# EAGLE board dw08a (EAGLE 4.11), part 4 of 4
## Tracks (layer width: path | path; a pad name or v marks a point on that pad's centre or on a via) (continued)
O_BAC10  (via drill 0.61) (continued)
  Bottom 0.152: v119.63,104.71 134.62,119.7 134.62,121.47 A14.E2 | v132.84,83 132.84,79.44 v128.02,74.61
O_BAC11  (via drill 0.61)
  Top 0.152: v155.45,25.08 155.45,28 150.5,32.96 150.5,34.73 138.81,46.42 138.81,46.93 137.03,48.7 137.03,50.48 136.78,50.74 136.78,52.64 133.6,55.82 133.6,56.96 v125.73,64.83 | v150.5,90.49 150.5,90.61 135.64,105.47 135.25,105.47 v130.68,110.05
  Bottom 0.152: v155.45,25.08 151.38,21.02 148.34,21.02 B13.S2 | v125.73,64.83 125.73,65.98 148.46,88.71 148.72,88.71 v150.5,90.49 | v130.68,110.05 132.84,112.2 132.84,113.35 134.62,115.13 A14.H2
O_BREAK  (via drill 0.61)
  Top 0.152: v92.46,67.88 66.8,93.53 65.79,93.53 64.01,95.31 61.47,95.31 60.33,96.46 59.44,96.46 A20.P2 | v96.9,67.88 108.08,56.71 109.98,56.71 v138.18,28.51
  Bottom 0.152: v92.46,67.88 v96.9,67.88 | v138.18,28.51 138.18,25.46 137.03,24.32 137.03,23.18 135.25,21.4 B14.S2
O_BRKRQ  (via drill 0.61)
  Top 0.152: v44.7,80.71 50.04,75.37 50.04,73.6 50.42,73.22 50.42,62.93 79.88,33.47 79.88,29.65 82.17,27.37 83.44,27.37 B18.P2
  Bottom 0.152: v44.7,80.71 44.7,87.57 59.82,102.68 59.82,103.69 57.15,106.36 56.01,105.22 55.12,105.22 53.98,106.36 55.12,107.5 56.39,107.5 58.04,109.16 A20.K2
O_CAINCR  (via drill 0.61)
  Top 0.152: v31.5,101.16 31.88,100.78 31.88,96.2 35.05,93.03 35.05,86.68 40.01,81.72 40.01,72.58 40.39,72.2 40.51,72.2 71.12,41.59 71.12,40.45 B19.K2
  Bottom 0.152: v31.5,101.16 32.89,102.55 A22.M2
O_DATA00  (via drill 0.61)
  Top 0.152: v40.77,72.96 40.77,81.47 35.43,86.81 35.43,93.15 32.26,96.33 32.26,101.66 31.5,102.42 31.5,112.46 43.18,124.14 42.67,124.65 A21.D2
  Bottom 0.152: v40.77,72.96 40.77,64.58 39.37,63.18 39.37,61.66 33.66,55.94 33.66,53.15 B22.E2
O_DATA01  (via drill 0.61)
  Top 0.152: v18.8,79.31 19.18,78.93 19.18,64.45 21.08,62.55 21.08,60.13 33.02,48.2 33.02,46.8 B22.H2
  Bottom 0.152: v18.8,79.31 18.8,93.41 43.94,118.56 43.94,119.7 45.72,121.47 A21.E2
O_DATA02  (via drill 0.61)
  Top 0.152: v18.41,77.79 18.8,77.41 18.8,64.33 19.56,63.56 19.56,58.23 33.02,44.77 33.02,40.45 B22.K2
  Bottom 0.152: v18.41,77.79 19.56,78.93 19.56,87.82 43.94,112.2 43.94,113.35 45.72,115.13 A21.H2
O_DATA03  (via drill 0.61)
  Top 0.152: v16.38,72.58 16.38,55.05 17.4,54.04 17.4,53.53 33.02,37.91 33.02,34.1 B22.M2
  Bottom 0.152: v16.38,72.58 17.02,72.58 22.35,77.92 22.35,84.26 43.94,105.86 43.94,107 45.72,108.78 A21.K2
O_DATA04
  Bottom 0.152: B22.P2 32.64,27.37 28.19,27.37 19.05,36.51 17.91,35.37 17.02,35.37 6.22,46.16 6.22,61.28 25.27,80.33 25.27,80.83 43.94,99.5 43.94,100.65 45.72,102.42 A21.M2
O_DATA05  (via drill 0.61)
  Top 0.152: v67.69,58.61 67.69,59.37 59.94,67.12 59.94,68.64 48.13,80.45 48.13,94.3 46.35,96.08 A21.P2
  Bottom 0.152: v67.69,58.61 33.66,24.57 33.66,21.4 B22.S2
O_DATA06  (via drill 0.61)
  Top 0.152: v46.61,81.09 46.61,83 47.75,84.14 47.75,88.33 46.35,89.72 A21.S2
  Bottom 0.152: v46.61,81.09 20.95,55.44 20.95,53.15 B23.E2
O_DATA07
  Bottom 0.152: B23.H2 19.94,46.42 18.54,46.42 14.99,49.97 24.51,59.5 24.51,60.52 28.45,64.45 28.45,64.96 43.94,80.45 43.94,85.79 43.18,86.55 A21.T2
O_DATA08
  Bottom 0.152: B23.K2 20.32,40.45 20.32,44.01 14.35,49.97 24.13,59.75 24.13,60.64 28.07,64.58 28.07,65.72 42.55,80.2 A21.V2
O_DATA09  (via drill 0.61)
  Top 0.152: v1.65,57.09 20.32,38.42 20.32,34.1 B23.M2
  Bottom 0.152: v1.65,57.09 1.65,95.31 28.07,121.73 28.07,122.87 29.84,124.65 A22.D2
O_DATA10
  Bottom 0.152: B23.P2 19.94,27.37 18.54,27.37 4.7,41.21 5.84,42.35 5.84,93.15 31.24,118.56 31.24,119.7 33.02,121.47 A22.E2
O_DATA11  (via drill 0.61)
  Top 0.152: v14.61,98.74 0.89,85.03 0.89,56.71 19.56,38.04 19.56,26.48 20.32,25.72 20.32,21.4 B23.S2
  Bottom 0.152: v14.61,98.74 29.72,113.86 30.99,113.86 32.64,115.51 A22.H2
O_DATAIN  (via drill 0.61)
  Top 0.152: v37.47,77.28 37.85,76.9 37.85,70.29 54.48,53.66 54.48,48.7 68.2,34.99 68.2,34.48 71.37,31.3 75.06,31.3 83.82,22.54 83.82,21.4 B18.S2
  Bottom 0.152: v37.47,77.28 37.47,80.33 37.59,80.45 37.59,83.63 55.12,101.16 56.39,101.16 58.04,102.81 A20.M2
O_EXTA0  (via drill 0.61)
  Top 0.152: v15.24,112.08 15.62,111.7 15.62,99.25 35.43,79.44 35.43,61.4 42.8,54.04 42.8,53.02 71.12,24.7 71.12,21.4 B19.S2
  Bottom 0.152: v15.24,112.08 17.02,113.86 18.29,113.86 19.94,115.51 A23.H2
O_EXTA1
  Top 0.152: B19.P2 70.74,27.37 69.98,27.37 68.96,28.38 68.45,28.38 67.18,29.65 67.18,35.5 54.1,48.58 54.1,53.53 37.47,70.17 37.47,76.14 36.7,76.9 36.7,78.68 16,99.38 16,125.67 17.4,127.06 18.54,125.92 18.54,124.78 20.32,123 A23.E2
O_EXTA2
  Top 0.152: B19.M2 71.12,34.1 71.12,37.27 70.99,37.4 70.99,37.66 38.23,70.42 38.23,77.66 16.38,99.5 16.38,123.89 17.14,124.65 A23.D2
O_INIT  (via drill 0.61)
  Top 0.152: v194.44,19.49 191.64,19.49 157.1,54.04 156.59,54.04 144.65,65.98 144.15,65.98 139.06,71.06 139.06,71.44 133.1,77.41 133.1,77.66 132.08,78.68 132.08,80.2 A14.V2 | v196.85,21.78 196.98,21.78 197.74,21.02 B09.S2
  Bottom 0.152: v194.44,19.49 194.56,19.49 v196.85,21.78
O_IOP1  (via drill 0.61)
  Top 0.152: v186.69,78.42 207.65,57.47 207.65,56.33 B08.D2 | v183.64,77.41 182.75,77.41 146.56,113.6 145.16,113.6 144.91,113.86 140.97,113.86 v140.46,114.36
  Bottom 0.152: v186.69,78.42 184.66,78.42 v183.64,77.41 | v140.46,114.36 138.18,114.36 137.03,113.22 137.03,112.08 135.25,110.3 A14.K2
O_IOP2  (via drill 0.61)
  Top 0.152: v185.8,54.17 176.02,63.94 172.59,63.94 167.64,68.9 163.07,68.9 162.94,69.03 162.43,69.03 162.31,69.15 161.93,69.15 161.67,69.41 161.42,69.41 151.89,78.93 151.89,81.47 139.57,93.79 139.57,94.3 135.25,98.61 135.25,102.42 A14.M2 | v190.5,55.56 193.17,52.9 193.17,52.39 194.06,51.5 195.33,51.5 v207.77,39.05
  Bottom 0.152: v185.8,54.17 189.1,54.17 v190.5,55.56 | v207.77,39.05 210.19,39.05 210.44,39.31 B08.K2
O_IOP4  (via drill 0.61)
  Top 0.152: v117.86,79.31 117.86,75.5 127.25,66.1 127.25,64.83 135,57.09 135.13,57.09 135.51,56.71 135.51,54.93 137.92,52.51 137.92,51.88 138.3,51.5 138.3,50.61 139.19,49.72 139.19,46.55 175.77,9.97 179.58,9.97 180.97,8.57 184.4,8.57 v187.96,5.02 | v208.28,22.04 209.42,22.04 210.44,21.02 B08.S2
  Bottom 0.152: v117.86,79.31 117.98,79.44 117.98,81.47 132.97,96.46 134.24,96.46 A14.P2 | v187.96,5.02 187.96,5.4 194.82,12.26 198.5,12.26 v208.28,22.04
O_IRQ  (via drill 0.61)
  Top 0.152: v104.52,74.36 104.52,81.22 86.23,99.5 86.23,100.65 84.45,102.42 A18.M2
  Bottom 0.152: v104.52,74.36 85.22,55.05 85.22,51.88 84.45,51.12 84.45,46.8 B18.H2
O_LINE  (via drill 0.61)
  Top 0.152: v93.98,44.51 93.98,46.16 93.34,46.8 93.34,47.43 76.33,64.45 76.33,65.72 v71.25,70.8
  Bottom 0.152: v93.98,44.51 93.47,44.01 93.22,44.01 84.45,35.24 84.45,34.1 B18.M2 | v71.25,70.8 80.64,80.2 A18.V2
O_MB00  (via drill 0.61)
  Top 0.152: v133.35,137.73 159.89,137.73 161.04,136.59 163.32,136.59 163.7,136.97 168.28,136.97 v180.72,124.52 | v201.68,139.51 204.98,139.51 210.69,133.79 213.87,133.79 218.57,129.09 218.57,127.95 220.34,126.17 A07.D2
  Bottom 0.152: v133.35,137.73 121.41,125.79 119.76,125.79 A15.D2 | v180.72,124.52 180.72,125.16 191.64,136.08 193.8,136.08 196.85,139.13 199.26,139.13 199.64,139.51 v201.68,139.51
O_MB01  (via drill 0.61)
  Top 0.152: v198.25,125.73 199.77,124.21 210.19,124.21 211.07,123.32 211.71,123.32 220.34,114.68 220.34,114.3 220.85,113.79 221.23,113.79 223.39,111.63 223.39,110.24 A07.K2 | v196.85,124.33 185.8,124.33 184.78,125.35 184.28,125.35 v169.93,139.7
  Bottom 0.152: v196.85,124.33 v198.25,125.73 | v169.93,139.7 141.35,139.7 125.98,124.33 124.59,124.33 122.94,122.68 A15.E2
O_MB02  (via drill 0.61)
  Top 0.152: v217.55,82.55 217.42,82.55 213.23,86.74 213.23,87.38 211.33,89.28 210.82,89.28 210.69,89.41 210.57,89.41 210.57,89.53 210.44,89.53 210.44,89.66 210.31,89.66 210.31,89.79 210.19,89.79 210.19,89.92 210.06,89.92 210.06,90.04 207.52,92.58 207.39,92.58 207.39,92.71 207.26,92.71 207.26,92.84 207.14,92.84 207.14,92.96 207.01,92.96 207.01,93.09 206.88,93.09 206.88,93.22 204.34,95.76 204.22,95.76 204.22,95.89 204.09,95.89 204.09,96.01 203.96,96.01 203.96,96.14 203.84,96.14 203.84,96.27 203.71,96.27 203.71,96.39 201.17,98.93 201.04,98.93 201.04,99.06 200.91,99.06 200.91,99.19 200.79,99.19 200.79,99.31 200.66,99.31 200.66,99.44 200.53,99.44 200.53,99.57 197.99,102.11 197.87,102.11 197.87,102.23 197.74,102.23 197.74,102.36 197.61,102.36 197.61,102.49 197.49,102.49 197.49,102.62 197.36,102.62 197.36,102.74 194.82,105.28 194.69,105.28 194.69,105.41 194.56,105.41 194.56,105.54 194.44,105.54 194.44,105.66 194.31,105.66 194.31,105.79 194.18,105.79 194.18,105.92 191.64,108.46 191.52,108.46 191.52,108.58 191.39,108.58 191.39,108.71 191.26,108.71 191.26,108.84 191.13,108.84 191.13,108.97 191.01,108.97 191.01,111.63 190.12,112.52 190.12,115.32 188.72,116.71 186.56,116.71 183.13,120.14 179.32,120.14 178.94,120.52 178.56,120.52 v173.1,125.98 | v166.5,120.4 163.83,120.4 151.38,132.84 v142.88,132.84
  Bottom 0.152: v217.55,82.55 223.39,88.39 223.39,89.79 A07.S2 | v173.1,125.98 172.09,125.98 v166.5,120.4 | v142.88,132.84 140.84,132.84 125.98,117.98 124.59,117.98 122.94,116.33 A15.H2
O_MB03  (via drill 0.61)
  Top 0.152: v132.59,91.25 122.56,101.28 122.56,102.42 A15.M2 | v184.4,137.35 184.91,137.35 209.04,113.22 209.04,112.08 210.82,110.3 A08.K2
  Bottom 0.152: v132.59,91.25 134.11,91.25 134.49,91.63 134.87,91.63 136.27,93.03 136.27,93.41 147.19,104.33 150.88,104.33 158.62,112.08 158.62,115.76 178.94,136.08 183.13,136.08 v184.4,137.35
O_MB03\  (via drill 0.61)
  Top 0.152: v147.45,101.28 140.72,108.01 134.37,108.01 132.59,109.79 132.08,109.79 129.67,112.2 127.38,109.92 122.94,109.92 A15.K2 | v186.31,138.11 193.68,138.11 204.34,127.44 205.61,127.44 207.26,125.79 A08.D2
  Bottom 0.152: v147.45,101.28 149.48,101.28 v186.31,138.11
O_MB04  (via drill 0.61)
  Top 0.152: v175.26,136.21 182.88,136.21 191.64,127.44 192.91,127.44 194.56,125.79 A09.D2
  Bottom 0.152: v175.26,136.21 175.13,136.08 172.59,136.08 153.54,117.03 147.19,117.03 122.56,92.39 122.56,91.25 A15.S2
O_MB04\  (via drill 0.61)
  Top 0.152: v200.03,103.06 200.03,102.93 201.8,101.16 202.06,101.16 206.5,96.71 206.5,96.46 208.15,94.81 208.41,94.81 210.82,92.39 210.82,91.25 A08.S2 | v190.75,93.92 190.25,93.92 v185.29,98.87 | v175.64,90.36 174.75,90.36 173.48,91.63 169.54,91.63 146.81,114.36 145.54,114.36 v142.88,117.03
  Bottom 0.152: v200.03,103.06 199.9,103.06 v190.75,93.92 | v185.29,98.87 184.15,98.87 v175.64,90.36 | v142.88,117.03 140.34,117.03 136.65,113.35 136.65,112.84 124.33,100.52 124.33,99.38 122.56,97.6 A15.P2
O_MB05  (via drill 0.61)
  Top 0.152: v151.51,57.59 147.19,57.59 145.16,59.63 144.27,59.63 123.32,80.58 119.76,80.58 A15.V2 | v193.68,93.79 193.68,93.66 194.82,92.52 196.09,92.52 197.74,90.87 A09.S2
  Bottom 0.152: v151.51,57.59 151.51,57.85 153.54,59.88 157.61,59.88 173.35,75.63 173.35,76.01 177.67,80.33 177.67,80.83 187.45,90.61 190.5,90.61 v193.68,93.79
O_MB05\  (via drill 0.61)
  Top 0.152: v145.03,110.81 147.07,110.81 147.19,110.68 148.08,110.68 155.07,103.69 155.07,103.31 v155.57,102.81 | v176.53,123.76 183.26,123.76 184.53,125.03 196.34,113.22 196.34,112.08 198.12,110.3 A09.K2
  Bottom 0.152: v145.03,110.81 121.92,87.69 119.76,87.69 A15.T2 | v155.57,102.81 v176.53,123.76
O_MB06
  Top 0.152: A10.K2 185.42,110.3 185.42,111.06 184.91,111.57 184.91,111.95 160.78,136.08 158.12,136.08 157.61,136.59 152.02,136.59 151.64,136.97 125.86,136.97 110.87,121.98 110.24,122.62 A16.E2
O_MB06\
  Top 0.152: A16.D2 107.06,125.86 111.51,125.86 128.4,142.75 128.78,142.75 131.7,139.83 140.34,139.83 141.1,139.06 166.12,139.06 166.88,138.3 167.51,138.3 176.4,129.41 176.91,129.41 178.82,127.51 180.21,127.51 181.86,125.86 A10.D2
O_MB07  (via drill 0.61)
  Top 0.152: v151.26,136.21 157.48,136.21 166.24,127.44 167.51,127.44 169.16,125.79 A11.D2
  Bottom 0.152: v151.26,136.21 147.96,132.91 144.02,132.91 135.64,124.52 134.11,124.52 120.27,110.68 115.44,110.68 114.68,109.92 110.24,109.92 A16.K2
O_MB07\  (via drill 0.61)
  Top 0.152: v184.15,89.34 142.75,130.75 142.37,130.75 142.11,131 140.46,131 138.56,132.91 124.97,132.91 108.97,116.9 109.22,116.65 A16.H2
  Bottom 0.152: v184.15,89.34 184.91,90.11 185.04,90.11 A10.S2
O_MB08  (via drill 0.61)
  Top 0.152: v139.06,117.67 139.7,117.03 141.73,117.03 144.53,114.24 145.03,114.24 145.29,113.98 146.69,113.98 169.8,90.87 172.34,90.87 A11.S2
  Bottom 0.152: v139.06,117.67 135.64,117.67 135.25,117.28 133.86,117.28 117.35,100.78 115.06,100.78 113.16,98.87 111.89,98.87 110.24,97.22 A16.P2
O_MB08\  (via drill 0.61)
  Top 0.152: v146.05,129.73 151.26,129.73 169.42,111.57 170.69,111.57 172.34,109.92 A11.K2
  Bottom 0.152: v146.05,129.73 139.7,123.38 134.49,123.38 114.68,103.57 110.24,103.57 A16.M2
O_MB09
  Bottom 0.152: A16.S2 108.84,90.11 108.08,90.11 107.06,89.09 106.55,89.09 105.28,87.82 105.28,86.81 110.36,81.72 125.09,96.46 126.11,96.46 147.07,117.41 147.57,117.41 153.54,123.38 154.81,123.38 156.46,125.03 A12.D2
O_MB10  (via drill 0.61)
  Top 0.152: v143.64,123 143.64,124.65 143.38,124.9 143.38,126.05 144.4,127.06 158.24,113.22 158.24,112.08 160.02,110.3 A12.K2
  Bottom 0.152: v143.64,123 140.08,119.44 140.08,117.54 133.22,110.68 133.22,110.17 110.74,87.69 107.06,87.69 A16.T2
O_MB11  (via drill 0.61)
  Top 0.152: v138.81,103.44 139.45,103.44 147.19,95.69 151.38,95.69 v157.73,89.34
  Bottom 0.152: v138.81,103.44 117.47,82.11 112.27,82.11 111.51,81.34 107.06,81.34 A16.V2 | v157.73,89.34 158.88,89.34 159.64,90.11 A12.S2
O_MBINCR
  Top 0.152: B19.E2 70.74,52.77 69.47,52.77 67.18,55.05 67.18,56.83 68.96,58.61 60.45,67.12 60.45,68.77 58.29,70.93 58.29,71.18 58.04,71.44 58.04,71.82 57.91,71.94 57.91,72.58 57.78,72.71 57.78,83.5 57.66,83.63 57.66,84.77 55.88,86.55 A20.T2
O_RUN
  Top 0.152: A18.S2 84.84,90.11 86.11,90.11 128.65,47.56 129.41,47.56 130.68,48.83 130.68,54.04 131.44,54.8 B14.D2
O_SKIP  (via drill 0.61)
  Top 0.152: v59.56,81.34 75.95,64.96 75.95,64.33 83.82,56.45 83.82,53.15 B18.E2
  Bottom 0.152: v59.56,81.34 59.56,82.49 68.07,91 68.07,91.89 82.04,105.86 82.04,107 83.82,108.78 A18.K2
O_TS1  (via drill 0.61)
  Top 0.152: v196.85,36.51 185.29,48.07 182.12,48.07 181.23,48.96 179.83,48.96 177.55,51.24 172.59,51.24 159,64.83 157.99,64.83 151.76,71.06 151.76,73.34 151.64,73.47 151.64,74.11 151.51,74.23 151.51,74.61 151.26,74.87 151.26,75.12 148.08,78.3 146.94,78.3 145.41,79.82 144.02,79.82 138.05,85.79 135.38,85.79 134.24,86.93 132.46,86.93 A14.T2
  Bottom 0.152: v196.85,36.51 196.85,37.66 198.12,38.92 B09.K2
O_TS3  (via drill 0.61)
  Top 0.152: v164.85,65.98 162.05,68.77 161.8,68.77 161.54,69.03 161.16,69.03 139.32,90.87 139.32,92.27 139.19,92.39 139.19,94.17 137.16,96.2 134.75,93.79 134.75,91.25 A14.S2 | v175.64,76.77 176.4,76.77 191.52,61.66 191.52,60.9 193.17,59.24 193.17,58.1 194.94,56.33 B09.D2
  Bottom 0.152: v164.85,65.98 v175.64,76.77
O_TT_INST  (via drill 0.61)
  Top 0.152: v84.2,92.14 85.22,92.14 v105.66,71.69 | v105.66,67.5 105.66,67.37 131.32,41.72 132.59,41.72 134.24,40.07 B14.K2
  Bottom 0.152: v84.2,92.14 81.28,89.22 81.28,88.08 A18.T2 | v105.66,71.69 v105.66,67.5
O_WCOV  (via drill 0.61)
  Top 0.152: v117.09,35.88 111.25,41.72 105.92,41.72 76.33,71.31 75.56,71.31 34.54,112.33 31.88,109.67 31.88,102.55 33.02,101.41 33.02,97.6 A22.P2
  Bottom 0.152: v117.09,35.88 117.09,36.13 118.62,37.66 119.89,37.66 121.54,39.31 B15.K2
VCC  (via drill 0.61)
  Top 0.381: v228.73,140.02 231.14,140.02 235.84,135.32 A06.A2 | v170.81,136.84 172.34,135.32 A11.A2 | v206.12,139.51 210.31,135.32 210.44,135.32 A08.A2 | v177.29,136.97 183.39,136.97 185.04,135.32 A10.A2 | v218.06,140.27 223.01,135.32 223.14,135.32 A07.A2 | v230,71.31 235.84,65.47 B06.A2 | v177.16,66.99 183.51,66.99 185.04,65.47 B10.A2 | v189.87,69.15 193.55,65.47 197.74,65.47 B09.A2 | v203.96,69.53 208.03,65.47 210.44,65.47 B08.A2 211.58,64.45 v212.85,63.18 | v219.96,68.9 223.27,65.6 B07.A2 | B23.A2 21.34,64.71 25.53,64.71 26.42,63.82 31.75,63.82 32.64,64.71 B22.A2 | v54.23,69.53 58.17,65.6 B20.A2 | v62.48,67.37 63.5,66.36 65.66,66.36 66.55,65.47 70.74,65.47 B19.A2 | v40.01,69.79 41.02,69.79 45.34,65.47 B21.A2 | B13.A2 147.07,65.6 144.53,68.14 v143.64,68.14 143.38,68.52 133.73,78.17 133.73,83.38 126.62,90.49 126.62,94.3 125.48,95.44 v125.48,97.22 | v154.18,71.18 159.77,65.6 B12.A2 | v113.41,66.48 120.52,66.48 121.54,65.47 B15.A2 | v90.93,70.55 91.06,70.55 96.14,65.47 B17.A2 | v104.9,69.66 108.97,65.6 B16.A2 | v128.78,71.18 134.37,65.6 B14.A2 | v77.85,71.06 83.44,65.47 B18.A2 | v160.4,77.28 163.7,77.28 163.83,77.15 164.47,77.15 164.59,77.03 164.85,77.03 164.97,76.9 165.35,76.9 165.74,76.52 165.99,76.52 169.93,72.58 169.93,70.42 171.07,69.28 171.07,68.26 172.72,66.61 172.72,65.85 B11.A2
  Bottom 0.381: v228.73,140.02 224.28,135.57 A07.A2 | v170.81,136.84 170.56,136.59 166.12,136.59 164.97,135.45 163.19,135.45 163.07,135.32 161.04,135.32 A12.A2 159.64,134.56 158.12,134.56 146.43,122.87 146.43,118.17 v125.48,97.22 | 202.95,139.51 201.42,141.03 194.82,141.03 189.74,135.95 188.59,135.95 188.34,135.7 187.58,135.7 187.2,135.32 186.44,135.32 A10.A2 | 202.95,139.51 198.88,135.45 A09.A2 | 202.95,139.51 v206.12,139.51 | v177.29,136.97 175.64,135.32 173.74,135.32 A11.A2 | v218.06,140.27 216.79,140.27 211.84,135.32 A08.A2 | v230,71.31 224.41,65.72 224.41,65.6 B07.A2 | v177.16,66.99 175.64,65.47 173.74,65.47 B11.A2 | v189.87,69.15 189.61,69.15 186.18,65.72 B10.A2 | v203.96,69.53 203.2,69.53 199.14,65.47 B09.A2 | v219.96,68.9 218.57,68.9 v212.85,63.18 | v54.23,69.53 50.16,65.47 46.74,65.47 B21.A2 | v62.48,67.37 62.36,67.37 61.59,66.61 61.09,66.61 59.44,64.96 B20.A2 | v40.01,69.79 35.69,65.47 34.04,65.47 B22.A2 | v143.64,68.14 138.3,68.14 135.64,65.47 B14.A2 | B13.A2 148.34,65.47 154.05,71.18 v154.18,71.18 154.56,71.44 v160.4,77.28 | v113.41,66.48 112.39,65.47 110.24,65.47 B16.A2 | v90.93,70.55 85.85,65.47 84.84,65.47 B18.A2 | v104.9,69.66 101.73,69.66 97.54,65.47 B17.A2 | v128.78,71.18 128.65,71.18 122.94,65.47 B15.A2 | v77.85,71.06 72.26,65.47 72.14,65.47 B19.A2

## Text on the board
Bottom: VRS | DW08A | DW08A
